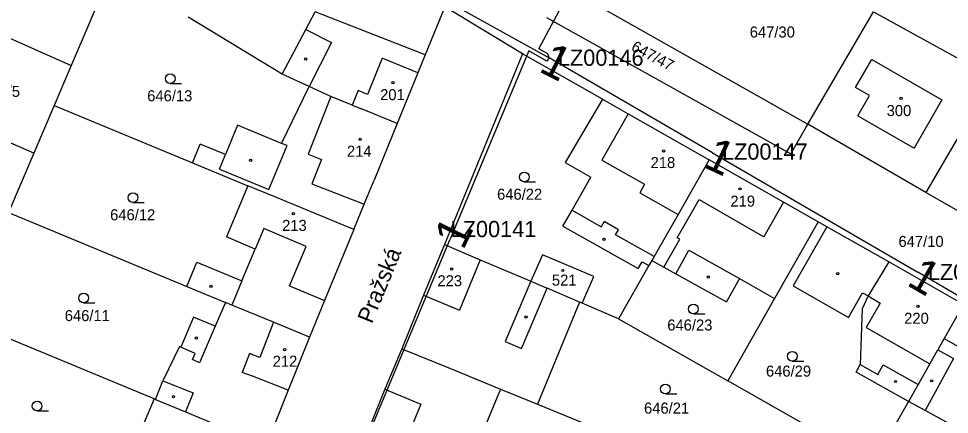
# Model space of a CAD drawing. Extents: x -738131 to -734179, y -1033447 to -1030078.
# Drawn here: x -736134.3 to -735990.9, y -1032608.3 to -1032547.3 of the extents above; entities that cross this region are included whole.
import ezdxf

# ---------------------------------------------------------------- set-up
doc = ezdxf.new("R2010")
doc.units = 0
for name, color, linetype in [('ftf_2010', 7, 'Continuous'), ('ftf_3010', 7, 'Continuous'), ('ftf_3010_ftf_3010_gtda_3015_gtda_3015_1', 7, 'Continuous'), ('ftf_nu', 7, 'Continuous'), ('Vrstva 1', 7, 'Continuous'), ('Vrstva 2', 7, 'Continuous'), ('Vrstva 3', 7, 'Continuous'), ('Vrstva 4', 7, 'Continuous'), ('Vrstva 5', 7, 'Continuous')]:
    doc.layers.add(name, color=color, linetype=linetype)

msp = doc.modelspace()

# ---------------------------------------------------------------- linework, layer by layer
at = {"layer": 'ftf_2010'}
for points in [[(-736052.56, -1032553.35), (-736052.75, -1032552.71), (-736054.14, -1032551.97), (-736049.81, -1032543.83), (-736050.76, -1032542.31), (-736034.95, -1032513.81)], [(-736085.03, -1032535.34), (-736052.56, -1032553.35)], [(-736052.56, -1032553.35), (-736052.88, -1032553.86), (-736055.65, -1032552.27), (-736067.87, -1032581.39)], [(-736027.35, -1032567.99), (-736052.56, -1032553.35)], [(-736027.35, -1032567.99), (-735995.75, -1032586.37)], [(-736084.05, -1032620.22), (-736067.87, -1032581.39)], [(-735965.62, -1032604.04), (-735995.75, -1032586.37)]]:
    msp.add_lwpolyline(points, dxfattribs=at)
at = {"layer": 'Vrstva 1'}
for points in [[(-736120.22, -1032540.58), (-736126.18, -1032554.51)], [(-736050.34, -1032542.27), (-736012.66, -1032563.59)], [(-736090.03, -1032548.97), (-736088.59, -1032546.26)], [(-736071.63, -1032552.88), (-736088.59, -1032546.26)], [(-736068.62, -1032545.49), (-736071.63, -1032552.88)], [(-736056.65, -1032552.72), (-736068.62, -1032545.49)], [(-736012.66, -1032563.59), (-736002.55, -1032546.24)], [(-736002.55, -1032546.24), (-735984.16, -1032556.39)], [(-736142.3, -1032547.39), (-736126.18, -1032554.51)], [(-736093.68, -1032555.85), (-736108.17, -1032547.08)], [(-736052.94, -1032547.14), (-736015.31, -1032568.13)], [(-736093.68, -1032555.85), (-736090.03, -1032548.97)], [(-736071.63, -1032552.88), (-736072.77, -1032555.67)], [(-736056.65, -1032552.72), (-736068.67, -1032582.11)], [(-736044.33, -1032559.74), (-736056.65, -1032552.72)], [(-736126.18, -1032554.51), (-736128.82, -1032560.69)], [(-736089.54, -1032557.76), (-736093.68, -1032555.85)], [(-736072.77, -1032555.67), (-736075.96, -1032563.47)], [(-736093.77, -1032566.53), (-736089.54, -1032557.76)], [(-736086.19, -1032559.3), (-736089.54, -1032557.76)], [(-736082.9, -1032560.64), (-736086.19, -1032559.3)], [(-736044.33, -1032559.74), (-736050.07, -1032569.47)], [(-736044.33, -1032559.74), (-736040.39, -1032561.98)], [(-735985.57, -1032558.82), (-735994.48, -1032574.13)], [(-736128.82, -1032560.69), (-736131.98, -1032568.07)], [(-736128.82, -1032560.69), (-736107.51, -1032569.52)], [(-736082.9, -1032560.64), (-736081.46, -1032561.23)], [(-736075.96, -1032563.47), (-736081.46, -1032561.23)], [(-736040.39, -1032561.98), (-736027.9, -1032569.07)], [(-736131.98, -1032568.07), (-736143.57, -1032563.03)], [(-736100.56, -1032563.72), (-736102.44, -1032568.25)], [(-736093.77, -1032566.53), (-736100.56, -1032563.72)], [(-736075.96, -1032563.47), (-736079.53, -1032572.2)], [(-736015.31, -1032568.13), (-736012.66, -1032563.59)], [(-735994.48, -1032574.13), (-736012.66, -1032563.59)], [(-736107.51, -1032569.52), (-736106.32, -1032566.64)], [(-736102.44, -1032568.25), (-736106.32, -1032566.64)], [(-736131.98, -1032568.07), (-736135.88, -1032577.19)], [(-736107.51, -1032569.52), (-736098.96, -1032573.06)], [(-736050.07, -1032569.47), (-736046.11, -1032571.72)], [(-736027.9, -1032569.07), (-736032.68, -1032577.49)], [(-736016.42, -1032575.59), (-736027.9, -1032569.07)], [(-736081.05, -1032575.92), (-736079.53, -1032572.2)], [(-736049.02, -1032576.84), (-736046.11, -1032571.72)], [(-736098.96, -1032573.06), (-736102.28, -1032580.94)], [(-736094.57, -1032574.88), (-736098.96, -1032573.06)], [(-735976.46, -1032584.42), (-735994.48, -1032574.13)], [(-736082.64, -1032579.82), (-736094.57, -1032574.88)], [(-736082.64, -1032579.82), (-736081.05, -1032575.92)], [(-736050.41, -1032579.29), (-736049.02, -1032576.84)], [(-736011.09, -1032578.62), (-736016.42, -1032575.59)], [(-736135.88, -1032577.19), (-736108.36, -1032588.58)], [(-736032.68, -1032577.49), (-736036.38, -1032583.99)], [(-736082.64, -1032579.82), (-736087.14, -1032590.74)], [(-736050.41, -1032579.29), (-736038.83, -1032585.83)], [(-736011.09, -1032578.62), (-736017.81, -1032590.45)], [(-736009.75, -1032579.38), (-736014.93, -1032588.51)], [(-736009.75, -1032579.38), (-736011.09, -1032578.62)], [(-736000.22, -1032584.8), (-736009.75, -1032579.38)], [(-736097.83, -1032582.82), (-736102.28, -1032580.94)], [(-736068.67, -1032582.11), (-736071.91, -1032589.94)], [(-736068.67, -1032582.11), (-736063.16, -1032584.47)], [(-736099.88, -1032587.73), (-736097.83, -1032582.82)], [(-736053.59, -1032583.69), (-736055.35, -1032587.8)], [(-736045.68, -1032587.07), (-736053.59, -1032583.69)], [(-736036.38, -1032583.99), (-736036.71, -1032584.58)], [(-736108.36, -1032588.58), (-736106.82, -1032584.86)], [(-736106.82, -1032584.86), (-736099.88, -1032587.73)], [(-736063.16, -1032584.47), (-736055.35, -1032587.8)], [(-736037.16, -1032585.37), (-736041.83, -1032593.58)], [(-736038.83, -1032585.83), (-736038.23, -1032584.77)], [(-736038.23, -1032584.77), (-736037.16, -1032585.37)], [(-736036.71, -1032584.58), (-736037.16, -1032585.37)], [(-736036.71, -1032584.58), (-736034.87, -1032585.6)], [(-736034.87, -1032585.6), (-736033.02, -1032586.62)], [(-735988.68, -1032591.36), (-736000.22, -1032584.8)], [(-736033.02, -1032586.62), (-736025.2, -1032590.95)], [(-736055.35, -1032587.8), (-736052.84, -1032588.87)], [(-736047.44, -1032591.18), (-736045.68, -1032587.07)], [(-736023.21, -1032587.35), (-736025.2, -1032590.95)], [(-736023.21, -1032587.35), (-736017.81, -1032590.45)], [(-736108.36, -1032588.58), (-736102.43, -1032591.04)], [(-736047.89, -1032590.99), (-736052.84, -1032588.87)], [(-736014.93, -1032588.51), (-736006.43, -1032593.37)], [(-736006.43, -1032593.37), (-736004.25, -1032589.55)], [(-736004.25, -1032589.55), (-736003.39, -1032590.06)], [(-736102.43, -1032591.04), (-736104.01, -1032594.72)], [(-736101.42, -1032591.45), (-736102.43, -1032591.04)], [(-736087.14, -1032590.74), (-736089.47, -1032596.4)], [(-736071.91, -1032589.94), (-736075.25, -1032598.19)], [(-736047.89, -1032590.99), (-736054.33, -1032606.75)], [(-736047.44, -1032591.18), (-736047.89, -1032590.99)], [(-736041.83, -1032593.58), (-736047.44, -1032591.18)], [(-736017.81, -1032590.45), (-736025.02, -1032603.13)], [(-736003.39, -1032590.06), (-736004.28, -1032592.04)], [(-735988.68, -1032591.36), (-735991.67, -1032596.63)], [(-736095.03, -1032594.1), (-736101.42, -1032591.45)], [(-736004.28, -1032592.04), (-736004.59, -1032600.63)], [(-736113.43, -1032605.92), (-736142.94, -1032593.68)], [(-736107.33, -1032593.31), (-736109.31, -1032597.95)], [(-736104.01, -1032594.72), (-736107.33, -1032593.31)], [(-736089.47, -1032596.4), (-736095.03, -1032594.1)], [(-736041.83, -1032593.58), (-736025.02, -1032603.13)], [(-736089.47, -1032596.4), (-736092.75, -1032604.58)], [(-735991.67, -1032596.63), (-735992.66, -1032598.37)], [(-736109.52, -1032597.85), (-736112.06, -1032603.12)], [(-736109.31, -1032597.95), (-736109.52, -1032597.85)], [(-736075.25, -1032598.19), (-736077.86, -1032604.44)], [(-736075.25, -1032598.19), (-736067.74, -1032601.26)], [(-735993.89, -1032600.53), (-735992.66, -1032598.37)], [(-736067.74, -1032601.26), (-736060.04, -1032604.41)], [(-736005.24, -1032601.78), (-736004.59, -1032600.63)], [(-735993.89, -1032600.53), (-735995.68, -1032603.68)], [(-735997.18, -1032606.32), (-736005.24, -1032601.78)], [(-736113.2, -1032606.01), (-736112.06, -1032603.12)], [(-736011.19, -1032610.99), (-736025.02, -1032603.13)], [(-735995.68, -1032603.68), (-735997.18, -1032606.32)], [(-736092.75, -1032604.58), (-736096.16, -1032613.08)], [(-736077.86, -1032604.44), (-736081.68, -1032613.9)], [(-736060.04, -1032604.41), (-736063.17, -1032611.98)], [(-736060.04, -1032604.41), (-736054.33, -1032606.75)], [(-736113.43, -1032605.92), (-736115.19, -1032610.17)], [(-736113.2, -1032606.01), (-736113.43, -1032605.92)], [(-736113.2, -1032606.01), (-736108.57, -1032607.93)], [(-736054.33, -1032606.75), (-736022.63, -1032619.73)], [(-735997.18, -1032606.32), (-736002.61, -1032615.87)], [(-735994.59, -1032607.73), (-735997.18, -1032606.32)], [(-736108.57, -1032607.93), (-736096.16, -1032613.08)], [(-735989.14, -1032610.69), (-735994.59, -1032607.73)]]:
    msp.add_lwpolyline(points, dxfattribs=at)
at = {"layer": 'Vrstva 3'}
for p, q in [((-736110.94, -1032557.31), (-736109.19, -1032557.31)), ((-736056.38, -1032572.46), (-736054.63, -1032572.46)), ((-736116.68, -1032575.65), (-736114.93, -1032575.65)), ((-736124.29, -1032591.12), (-736122.54, -1032591.12)), ((-736030.31, -1032592.81), (-736028.56, -1032592.81)), ((-736015.07, -1032600.1), (-736013.32, -1032600.1)), ((-736034.63, -1032605.13), (-736032.88, -1032605.13)), ((-736131.45, -1032607.78), (-736129.7, -1032607.78))]:
    msp.add_line(p, q, dxfattribs=at)
for centre in [(-736110.94, -1032556.56), (-736056.38, -1032571.71), (-736116.68, -1032574.9), (-736124.29, -1032590.37), (-736030.31, -1032592.06), (-736015.07, -1032599.35), (-736034.63, -1032604.38), (-736131.45, -1032607.03)]:
    msp.add_circle(centre, 0.75, dxfattribs=at)
at = {"layer": 'Vrstva 4'}
for points in [[(-736090.03, -1032548.97), (-736086.07, -1032551.01)], [(-736086.07, -1032551.01), (-736089.54, -1032557.76)], [(-736078.26, -1032553.42), (-736080.55, -1032559)], [(-736072.77, -1032555.67), (-736078.26, -1032553.42)], [(-736005.32, -1032557.93), (-736002.83, -1032553.61)], [(-736002.83, -1032553.61), (-735992.03, -1032559.84)], [(-736003.16, -1032559.18), (-736005.32, -1032557.93)], [(-736086.19, -1032559.3), (-736089.68, -1032568.19)], [(-736081.99, -1032558.41), (-736082.9, -1032560.64)], [(-736080.55, -1032559), (-736081.99, -1032558.41)], [(-736004.95, -1032562.29), (-736003.16, -1032559.18)], [(-735992.03, -1032559.84), (-735996.31, -1032567.27)], [(-736040.39, -1032561.98), (-736044.4, -1032569.13)], [(-736004.95, -1032562.29), (-735996.31, -1032567.27)], [(-736095.73, -1032573.65), (-736092.93, -1032566.88)], [(-736092.93, -1032566.88), (-736093.77, -1032566.53)], [(-736103.36, -1032570.49), (-736102.44, -1032568.25)], [(-736089.68, -1032568.19), (-736087.61, -1032569)], [(-736087.61, -1032569), (-736089.09, -1032572.77)], [(-736044.4, -1032569.13), (-736037.83, -1032572.82)], [(-736103.36, -1032570.49), (-736095.73, -1032573.65)], [(-736089.09, -1032572.77), (-736081.05, -1032575.92)], [(-736037.83, -1032572.82), (-736038.59, -1032574.18)], [(-736038.59, -1032574.18), (-736032.68, -1032577.49)], [(-736032.82, -1032581.07), (-736029.44, -1032575.2)], [(-736029.44, -1032575.2), (-736019.46, -1032580.95)], [(-736049.02, -1032576.84), (-736044.53, -1032579.39)], [(-736016.42, -1032575.59), (-736019.46, -1032580.95)], [(-736096.5, -1032579.66), (-736097.83, -1032582.82)], [(-736089.99, -1032582.41), (-736096.5, -1032579.66)], [(-736044.08, -1032578.6), (-736044.53, -1032579.39)], [(-736041.86, -1032579.86), (-736044.08, -1032578.6)], [(-736042.3, -1032580.64), (-736041.86, -1032579.86)], [(-736036.38, -1032583.99), (-736042.3, -1032580.64)], [(-736034.87, -1032585.6), (-736032.4, -1032581.31)], [(-736032.4, -1032581.31), (-736032.82, -1032581.07)], [(-736092.56, -1032588.5), (-736089.99, -1032582.41)], [(-736033.02, -1032586.62), (-736031.03, -1032583.02)], [(-736031.03, -1032583.02), (-736023.21, -1032587.35)], [(-736063.16, -1032584.47), (-736066.37, -1032592.23)], [(-736000.22, -1032584.8), (-736003.39, -1032590.06)], [(-736099.88, -1032587.73), (-736101.42, -1032591.45)], [(-736055.35, -1032587.8), (-736059.3, -1032597.07)], [(-736092.56, -1032588.5), (-736087.14, -1032590.74)], [(-736056.79, -1032598.14), (-736052.84, -1032588.87)], [(-736071.91, -1032589.94), (-736066.37, -1032592.23)], [(-736001.55, -1032591.14), (-736003.71, -1032594.91)], [(-736003.39, -1032590.06), (-736001.55, -1032591.14)], [(-736095.03, -1032594.1), (-736097.14, -1032599.52)], [(-736104.01, -1032594.72), (-736106, -1032599.37)], [(-736003.71, -1032594.91), (-735993.89, -1032600.53)], [(-736059.3, -1032597.07), (-736056.79, -1032598.14)], [(-735991.67, -1032596.63), (-735985.49, -1032600.14)], [(-736107.08, -1032598.9), (-736109.31, -1032597.95)], [(-735992.66, -1032598.37), (-735990.24, -1032599.68)], [(-736107.5, -1032599.87), (-736107.08, -1032598.9)], [(-736106.41, -1032600.34), (-736107.5, -1032599.87)], [(-736106, -1032599.37), (-736106.41, -1032600.34)], [(-736098.7, -1032598.92), (-736099.83, -1032601.83)], [(-736097.14, -1032599.52), (-736098.7, -1032598.92)], [(-735990.24, -1032599.68), (-735994.59, -1032607.73)], [(-736004.59, -1032600.63), (-736001.9, -1032602.15)], [(-736001.9, -1032602.15), (-736001.06, -1032600.65)], [(-736001.06, -1032600.65), (-735995.68, -1032603.68)], [(-736098.27, -1032602.44), (-736099.83, -1032601.83)], [(-736092.75, -1032604.58), (-736098.27, -1032602.44)], [(-736112.06, -1032603.12), (-736107.4, -1032604.97)], [(-736107.4, -1032604.97), (-736108.57, -1032607.93)], [(-736077.86, -1032604.44), (-736072.32, -1032606.71)], [(-736072.32, -1032606.71), (-736076.19, -1032616.14)]]:
    msp.add_lwpolyline(points, dxfattribs=at)
at = {"layer": 'Vrstva 5'}
for centre in [(-736090.06, -1032553.54), (-736076.59, -1032557.17), (-735998.32, -1032559.58), (-736081.67, -1032565.93), (-736034.9, -1032567.7), (-736098.53, -1032569.15), (-736023.15, -1032573.54), (-736091.98, -1032577.36), (-736044.11, -1032581.31), (-736067.57, -1032585.9), (-736050.43, -1032586.13), (-736028.02, -1032587.15), (-736008.07, -1032586.62), (-736104.67, -1032588.56), (-735995.72, -1032591.64), (-736056.1, -1032593.29), (-736106.91, -1032596.53), (-736093.31, -1032598.35), (-735999.17, -1032603.24), (-735993.58, -1032603.14), (-736110.43, -1032605.57)]:
    msp.add_circle(centre, 0.175, dxfattribs=at)

# ---------------------------------------------------------------- texts
at = {"layer": 'ftf_3010'}
for rotation, p in [(333.2302, (-736054.31, -1032555.38)), (334.9994, (-736029.03, -1032570.07)), (63.8206, (-736065.82, -1032583.12)), (329.6966, (-735997.62, -1032588.29))]:
    msp.add_text('1', height=5.2, rotation=rotation, dxfattribs=at).set_placement(p)
at = {"layer": 'ftf_3010_ftf_3010_gtda_3015_gtda_3015_1'}
for s, p in [('LZ00146', (-736051.19, -1032554.58)), ('LZ00147', (-736025.9, -1032569.05)), ('LZ00141', (-736067.72, -1032580.99)), ('LZ00148', (-735994.18, -1032587.61))]:
    msp.add_text(s, height=2.5, dxfattribs=at).set_placement(p)
at = {"layer": 'ftf_nu'}
msp.add_text('Pražská', height=2.5, rotation=67.7055, dxfattribs=at).set_placement((-736079.86, -1032594.45))
at = {"layer": 'Vrstva 2'}
for s, p in [('647/30', (-736021.63, -1032550.22)), ('646/5', (-736139.77, -1032559.37)), ('646/13', (-736114.48, -1032560.05)), ('201', (-736078.59, -1032559.87)), ('300', (-736000.53, -1032562.33)), ('214', (-736083.7, -1032568.59)), ('218', (-736036.91, -1032570.34)), ('646/22', (-736060.57, -1032575.22)), ('219', (-736024.61, -1032576.29)), ('646/12', (-736120.2, -1032578.39)), ('213', (-736093.69, -1032580.03)), ('647/10', (-735998.71, -1032582.5)), ('223', (-736069.76, -1032588.56)), ('521', (-736052.12, -1032588.46)), ('646/11', (-736127.19, -1032593.93)), ('220', (-735997.83, -1032594.35)), ('646/23', (-736034.34, -1032595.38)), ('212', (-736095.15, -1032600.96)), ('646/29', (-736019.13, -1032602.49)), ('646/21', (-736037.92, -1032608.19))]:
    msp.add_text(s, height=1.7, dxfattribs=at).set_placement(p)
msp.add_text('647/47', height=1.7, rotation=331.791, dxfattribs=at).set_placement((-736040.04, -1032552.13))

doc.saveas('drawing.dxf')
